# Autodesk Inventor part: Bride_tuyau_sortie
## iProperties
Shininess: 64.0
Length Units: 11269
Angle Units: 11279
Time Units: 11290
Mass Units: 11283
Length Display Precision: 3
Angle Display Precision: 2
Compacted: True
Part Number: Bride_tuyau_sortie
Document SubType Name: Modeling
Created: 2008-02
Material: Par défaut
Designer: Pascal
Density: 0.0
Volumn: 0.0
Area: 0.0
PropertySet Name: Model Information
Control State: 0
Master: False
Checked Out: False
DESIGNATION: Ligne tuyauterie sortie
Author: Pascal
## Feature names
1. Extrusion1
2. Extrusion2
3. Réseau circulaire1 [Circular Pattern]
4. Révolution1 [Revolution]
5. Balayage3
6. Extrusion5
7. Extrusion6
8. Réseau circulaire4 [Circular Pattern]
